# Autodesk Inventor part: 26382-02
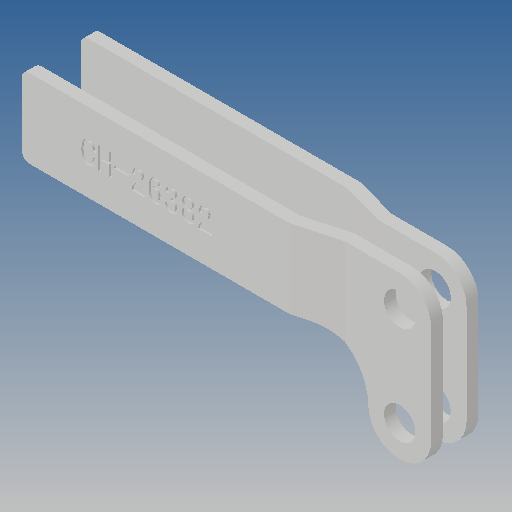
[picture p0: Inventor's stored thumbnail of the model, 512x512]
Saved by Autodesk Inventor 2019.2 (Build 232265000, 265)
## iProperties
Created: 2012-09
Part Number: 26382-02
Material: Ogólny
Document SubType Name: Modeling
Designer: CADENGINEERING4
Density: 1 g/cm^3
Appearance: Domyślna
Author: CADENGINEERING4
Revision Number: ÈÎºÎ
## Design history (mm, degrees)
feature "ÇÐ³ý-À­Éì3"
feature "ÇÐ³ý-À­Éì5"
node "Bryła1"
node "Bryła2"
